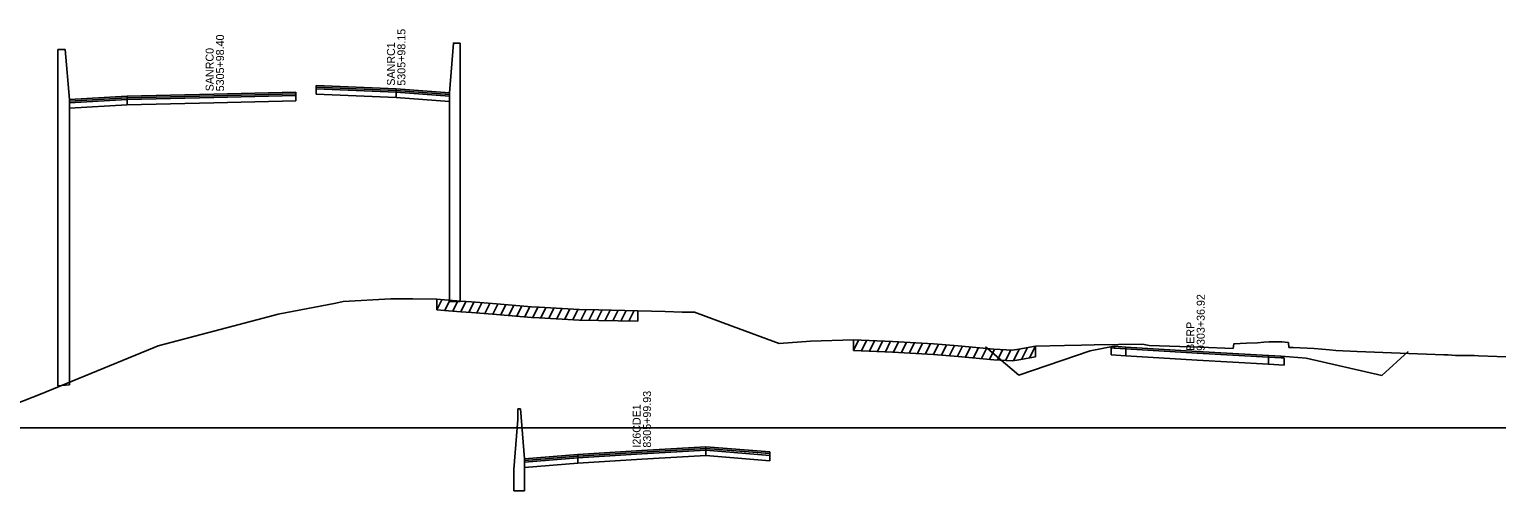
# Model space of a CAD drawing. Extents: x 1017 to 19997, y -1947 to 50737.
# Drawn here: x 12680.6 to 12955.6, y 5988.2 to 6074.8 of the extents above; entities that cross this region are included whole.
import ezdxf

# ---------------------------------------------------------------- set-up
doc = ezdxf.new("R2010")
doc.units = 0
for name, color, linetype in [('RD_GPK_XS_Cell', 7, 'Continuous'), ('RD_XS_Base', 7, 'Continuous'), ('RD_XS_ExGround', 7, 'Continuous'), ('RD_XS_ExPaveRet', 7, 'Continuous'), ('RD_XS_Greenside', 7, 'Continuous'), ('RD_XS_MedBWall', 7, 'Continuous'), ('RD_XS_Pave', 7, 'Continuous'), ('RD_XS_PaveOvlay', 7, 'Continuous'), ('RD_XS_TieSlope', 7, 'Continuous'), ('RD_XS_TX_Notes', 7, 'Continuous')]:
    doc.layers.add(name, color=color, linetype=linetype)

msp = doc.modelspace()

# ---------------------------------------------------------------- linework, layer by layer
at = {"layer": 'RD_GPK_XS_Cell'}
msp.add_line((12600, 6000), (13200, 6000), dxfattribs=at)
at = {"layer": 'RD_XS_Base'}
for points in [[(12734.34, 6063.58), (12749.34, 6062.98)], [(12734.34, 6062.58), (12734.34, 6063.58)], [(12698.94, 6061.59), (12688.13, 6060.98)], [(12688.13, 6060.98), (12688.13, 6059.98)], [(12698.94, 6061.59), (12715.16, 6061.94), (12730.55, 6062.33)], [(12698.94, 6060.59), (12698.94, 6061.59)], [(12730.55, 6061.33), (12715.16, 6060.94), (12698.94, 6060.59)], [(12730.55, 6062.33), (12730.55, 6061.33)], [(12749.34, 6061.98), (12734.34, 6062.58)], [(12749.34, 6062.98), (12759.34, 6062.19)], [(12749.34, 6061.98), (12749.34, 6062.98)], [(12759.34, 6061.19), (12749.34, 6061.98)], [(12759.34, 6062.19), (12759.34, 6061.19)], [(12688.13, 6059.98), (12698.94, 6060.59)], [(12883.33, 6015.01), (12883.33, 6013.67)], [(12886.11, 6014.84), (12883.33, 6015.01)], [(12886.11, 6014.84), (12899.49, 6014.03), (12912.86, 6013.27)], [(12886.11, 6013.5), (12886.11, 6014.84)], [(12883.33, 6013.67), (12886.11, 6013.5)], [(12912.86, 6011.95), (12899.49, 6012.7), (12886.11, 6013.5)], [(12912.86, 6013.27), (12912.86, 6011.95)], [(12912.86, 6013.27), (12915.19, 6013.15), (12915.78, 6013.12)], [(12915.78, 6011.78), (12912.86, 6011.95)], [(12915.78, 6013.12), (12915.78, 6011.78)], [(12783.39, 5994.38), (12795.39, 5995.1), (12807.39, 5995.82)], [(12807.39, 5994.82), (12795.39, 5994.1), (12783.39, 5993.38)], [(12807.39, 5995.82), (12807.39, 5994.82)], [(12819.39, 5994.84), (12807.39, 5995.82)], [(12807.39, 5994.82), (12819.39, 5993.84)], [(12819.39, 5993.84), (12819.39, 5994.84)], [(12783.39, 5994.38), (12773.38, 5993.58)], [(12773.38, 5993.58), (12773.38, 5992.58)], [(12773.38, 5992.58), (12783.39, 5993.38)], [(12783.39, 5993.38), (12783.39, 5994.38)]]:
    msp.add_lwpolyline(points, dxfattribs=at)
at = {"layer": 'RD_XS_ExGround'}
msp.add_lwpolyline([(12673.37, 6002.71), (12682.68, 6006.33), (12704.01, 6015.09), (12704.73, 6015.37), (12725.59, 6020.86), (12727.21, 6021.34), (12738.06, 6023.39), (12739.42, 6023.67), (12748.33, 6024.2), (12752.47, 6024.18), (12756.94, 6024.13), (12758.42, 6024), (12761.47, 6023.77), (12763.48, 6023.62), (12768.17, 6023.25), (12774.73, 6022.71), (12776.16, 6022.63), (12783.67, 6022.2), (12787.28, 6022.13), (12794.65, 6021.98), (12799.75, 6021.83), (12802.92, 6021.73), (12805.26, 6021.72), (12812.32, 6019.09), (12821.12, 6015.8), (12827.01, 6016.28), (12835.03, 6016.48), (12842.34, 6016.22), (12850.04, 6015.78), (12854.69, 6015.41), (12861.38, 6014.77), (12864.85, 6014.58), (12866.06, 6014.75), (12869.16, 6015.32), (12874.58, 6015.45), (12877.78, 6015.5), (12880.18, 6015.6), (12889.21, 6015.69), (12890.48, 6015.45), (12900.03, 6015.16), (12906.2, 6014.89), (12906.35, 6015.78), (12908.71, 6015.86), (12910.77, 6015.97), (12911.97, 6016.09), (12912.96, 6016.14), (12915.3, 6016.11), (12916.55, 6015.99), (12916.67, 6015.1), (12917.46, 6015.06), (12921.37, 6014.86), (12924.23, 6014.62), (12925.42, 6014.51), (12929.42, 6014.33), (12937.5, 6013.99), (12945.68, 6013.71), (12946.53, 6013.68), (12947.85, 6013.56), (12949.2, 6013.57), (12950.37, 6013.55), (12951.39, 6013.54), (12952.18, 6013.53), (12962.48, 6013.12)], dxfattribs=at)
at = {"layer": 'RD_XS_ExPaveRet'}
for p, q in [((12756.94, 6022.13), (12756.94, 6024.13)), ((12756.94, 6022.13), (12757.9, 6024.04)), ((12758.44, 6021.99), (12759.4, 6023.92)), ((12759.94, 6021.88), (12760.9, 6023.81)), ((12761.44, 6021.77), (12762.4, 6023.7)), ((12762.94, 6021.66), (12763.9, 6023.59)), ((12764.44, 6021.55), (12765.4, 6023.47)), ((12765.94, 6021.43), (12766.9, 6023.35)), ((12767.44, 6021.31), (12768.4, 6023.23)), ((12768.94, 6021.19), (12769.9, 6023.11)), ((12770.44, 6021.07), (12771.4, 6022.99)), ((12771.94, 6020.94), (12772.9, 6022.86)), ((12773.44, 6020.82), (12774.4, 6022.74)), ((12774.94, 6020.7), (12775.91, 6022.64)), ((12776.44, 6020.61), (12777.41, 6022.56)), ((12777.94, 6020.53), (12778.91, 6022.47)), ((12779.44, 6020.44), (12780.41, 6022.39)), ((12780.94, 6020.36), (12781.91, 6022.3)), ((12782.44, 6020.27), (12783.41, 6022.21)), ((12783.94, 6020.19), (12784.93, 6022.17)), ((12756.94, 6022.13), (12758.42, 6022)), ((12758.42, 6022), (12761.47, 6021.77)), ((12761.47, 6021.77), (12763.48, 6021.62)), ((12763.48, 6021.62), (12768.17, 6021.25)), ((12768.17, 6021.25), (12774.73, 6020.71)), ((12774.73, 6020.71), (12776.16, 6020.63)), ((12776.16, 6020.63), (12783.67, 6020.2)), ((12783.67, 6020.2), (12787.28, 6020.13)), ((12785.44, 6020.16), (12786.43, 6022.14)), ((12786.94, 6020.13), (12787.93, 6022.11)), ((12787.28, 6020.13), (12794.65, 6019.98)), ((12788.44, 6020.1), (12789.43, 6022.08)), ((12789.94, 6020.07), (12790.93, 6022.05)), ((12791.44, 6020.04), (12792.43, 6022.02)), ((12792.94, 6020.01), (12793.93, 6021.99)), ((12794.65, 6021.98), (12794.65, 6019.98)), ((12835.03, 6014.48), (12835.03, 6016.48)), ((12835.03, 6014.48), (12836.02, 6016.45)), ((12835.03, 6014.48), (12842.34, 6014.22)), ((12836.53, 6014.43), (12837.52, 6016.39)), ((12838.03, 6014.37), (12839.02, 6016.34)), ((12839.53, 6014.32), (12840.52, 6016.29)), ((12841.03, 6014.27), (12842.02, 6016.23)), ((12842.34, 6014.22), (12850.04, 6013.78)), ((12842.53, 6014.21), (12843.51, 6016.16)), ((12844.03, 6014.13), (12845.01, 6016.07)), ((12845.53, 6014.04), (12846.51, 6015.98)), ((12847.03, 6013.95), (12848.01, 6015.89)), ((12848.53, 6013.86), (12849.51, 6015.81)), ((12850.03, 6013.78), (12851, 6015.7)), ((12851.53, 6013.66), (12852.5, 6015.58)), ((12853.03, 6013.54), (12854, 6015.46)), ((12854.53, 6013.42), (12855.49, 6015.33)), ((12856.03, 6013.28), (12856.99, 6015.19)), ((12857.53, 6013.14), (12858.49, 6015.05)), ((12859.03, 6013), (12859.99, 6014.9)), ((12860.53, 6012.85), (12861.49, 6014.77)), ((12862.03, 6012.74), (12863.01, 6014.68)), ((12863.53, 6012.65), (12864.51, 6014.6)), ((12865.03, 6012.6), (12866.12, 6014.76)), ((12866.53, 6012.84), (12867.64, 6015.04)), ((12868.03, 6013.12), (12869.14, 6015.32)), ((12869.16, 6015.32), (12869.16, 6013.32)), ((12850.04, 6013.78), (12854.69, 6013.41)), ((12854.69, 6013.41), (12861.38, 6012.77)), ((12861.38, 6012.77), (12864.85, 6012.58)), ((12864.85, 6012.58), (12866.06, 6012.75)), ((12866.06, 6012.75), (12869.16, 6013.32))]:
    msp.add_line(p, q, dxfattribs=at)
at = {"layer": 'RD_XS_Greenside'}
for points in [[(12879.43, 6014.44), (12866.06, 6009.85)], [(12883.89, 6015.29), (12879.43, 6014.44)], [(12915.19, 6013.46), (12919.9, 6013.07)], [(12919.9, 6013.07), (12934.04, 6009.83)]]:
    msp.add_lwpolyline(points, dxfattribs=at)
at = {"layer": 'RD_XS_MedBWall'}
for points in [[(12761.34, 6072.16), (12760.09, 6072.16), (12759.34, 6062.82)], [(12761.34, 6023.67), (12761.34, 6072.16)], [(12685.97, 6007.91), (12685.97, 6071)], [(12685.97, 6071), (12687.32, 6070.97), (12688.13, 6061.62)], [(12688.13, 6061.62), (12688.13, 6008.06)], [(12759.34, 6062.82), (12759.34, 6023.66)], [(12759.34, 6023.66), (12761.34, 6023.67)], [(12688.13, 6008.06), (12685.97, 6007.91)], [(12773.38, 5994.21), (12772.63, 6003.55), (12772.13, 6003.55)], [(12772.13, 6003.55), (12772.13, 6001.55)], [(12772.13, 6001.55), (12771.38, 5992.21)], [(12771.38, 5992.21), (12771.38, 5988.21)], [(12773.38, 5988.21), (12773.38, 5994.21)], [(12771.38, 5988.21), (12773.38, 5988.21)]]:
    msp.add_lwpolyline(points, dxfattribs=at)
at = {"layer": 'RD_XS_Pave'}
for points in [[(12749.34, 6063.3), (12734.34, 6063.9)], [(12734.34, 6063.9), (12734.34, 6063.58)], [(12734.34, 6063.58), (12749.34, 6062.98)], [(12698.94, 6061.91), (12688.13, 6061.3)], [(12688.13, 6060.98), (12698.94, 6061.59)], [(12688.13, 6061.3), (12688.13, 6060.98)], [(12730.55, 6062.65), (12715.16, 6062.26), (12698.94, 6061.91)], [(12698.94, 6061.59), (12715.16, 6061.94), (12730.55, 6062.33)], [(12698.94, 6061.91), (12698.94, 6061.59)], [(12730.55, 6062.33), (12730.55, 6062.65)], [(12749.34, 6062.98), (12749.34, 6063.3)], [(12749.34, 6063.3), (12759.34, 6062.51)], [(12759.34, 6062.19), (12749.34, 6062.98)], [(12759.34, 6062.51), (12759.34, 6062.19)], [(12773.38, 5993.9), (12783.39, 5994.7)], [(12807.39, 5996.14), (12795.39, 5995.42), (12783.39, 5994.7)], [(12783.39, 5994.38), (12795.39, 5995.1), (12807.39, 5995.82)], [(12783.39, 5994.7), (12783.39, 5994.38)], [(12807.39, 5995.82), (12807.39, 5996.14)], [(12807.39, 5996.14), (12819.39, 5995.17)], [(12819.39, 5994.84), (12807.39, 5995.82)], [(12819.39, 5995.17), (12819.39, 5994.84)], [(12783.39, 5994.38), (12773.38, 5993.58)], [(12773.38, 5993.58), (12773.38, 5993.9)]]:
    msp.add_lwpolyline(points, dxfattribs=at)
at = {"layer": 'RD_XS_PaveOvlay'}
for points in [[(12734.34, 6064.21), (12749.34, 6063.62)], [(12734.34, 6063.9), (12734.34, 6064.21)], [(12749.34, 6063.3), (12734.34, 6063.9)], [(12749.34, 6063.62), (12749.34, 6063.3)], [(12749.34, 6063.62), (12759.34, 6062.82)], [(12698.94, 6062.22), (12688.13, 6061.62)], [(12688.13, 6061.3), (12698.94, 6061.91)], [(12688.13, 6061.62), (12688.13, 6061.3)], [(12698.94, 6062.22), (12715.16, 6062.57), (12730.55, 6062.97)], [(12730.55, 6062.65), (12715.16, 6062.26), (12698.94, 6061.91)], [(12698.94, 6061.91), (12698.94, 6062.22)], [(12730.55, 6062.97), (12730.55, 6062.65)], [(12759.34, 6062.51), (12749.34, 6063.3)], [(12759.34, 6062.82), (12759.34, 6062.51)], [(12883.89, 6015.29), (12883.89, 6014.97)], [(12886.11, 6015.15), (12883.89, 6015.29)], [(12883.89, 6014.97), (12886.11, 6014.84)], [(12886.11, 6015.15), (12899.49, 6014.35), (12912.86, 6013.58)], [(12886.11, 6014.84), (12886.11, 6015.15)], [(12912.86, 6013.58), (12912.86, 6013.27)], [(12912.86, 6013.58), (12915.19, 6013.46)], [(12915.19, 6013.15), (12912.86, 6013.27)], [(12915.19, 6013.46), (12915.19, 6013.15)], [(12783.39, 5995.01), (12773.38, 5994.21)], [(12773.38, 5993.9), (12783.39, 5994.7)], [(12783.39, 5995.01), (12795.39, 5995.73), (12807.39, 5996.45)], [(12807.39, 5996.14), (12795.39, 5995.42), (12783.39, 5994.7)], [(12783.39, 5994.7), (12783.39, 5995.01)], [(12807.39, 5996.45), (12807.39, 5996.14)], [(12807.39, 5996.45), (12819.39, 5995.49)], [(12819.39, 5995.17), (12807.39, 5996.14)], [(12819.39, 5995.49), (12819.39, 5995.17)], [(12773.38, 5994.21), (12773.38, 5993.9)]]:
    msp.add_lwpolyline(points, dxfattribs=at)
at = {"layer": 'RD_XS_TieSlope'}
for points in [[(12866.06, 6009.85), (12859.8, 6015.19)], [(12934.04, 6009.83), (12939.02, 6014.33)]]:
    msp.add_lwpolyline(points, dxfattribs=at)

# ---------------------------------------------------------------- texts
at = {"layer": 'RD_XS_TX_Notes'}
for s, p in [(' 5305+98.15', (12751.08, 6063.63)), (' 5305+98.40', (12717.09, 6062.57)), (' SANRC1', (12749.12, 6063.63)), (' SANRC0', (12715.14, 6062.57)), (' 9303+36.92', (12900.88, 6013.87)), (' BERP', (12898.93, 6013.87)), (' 8305+99.93', (12797.11, 5995.73)), (' I26CDE1', (12795.16, 5995.73))]:
    msp.add_text(s, height=1.5, rotation=90, dxfattribs=at).set_placement(p)

doc.saveas('drawing.dxf')
